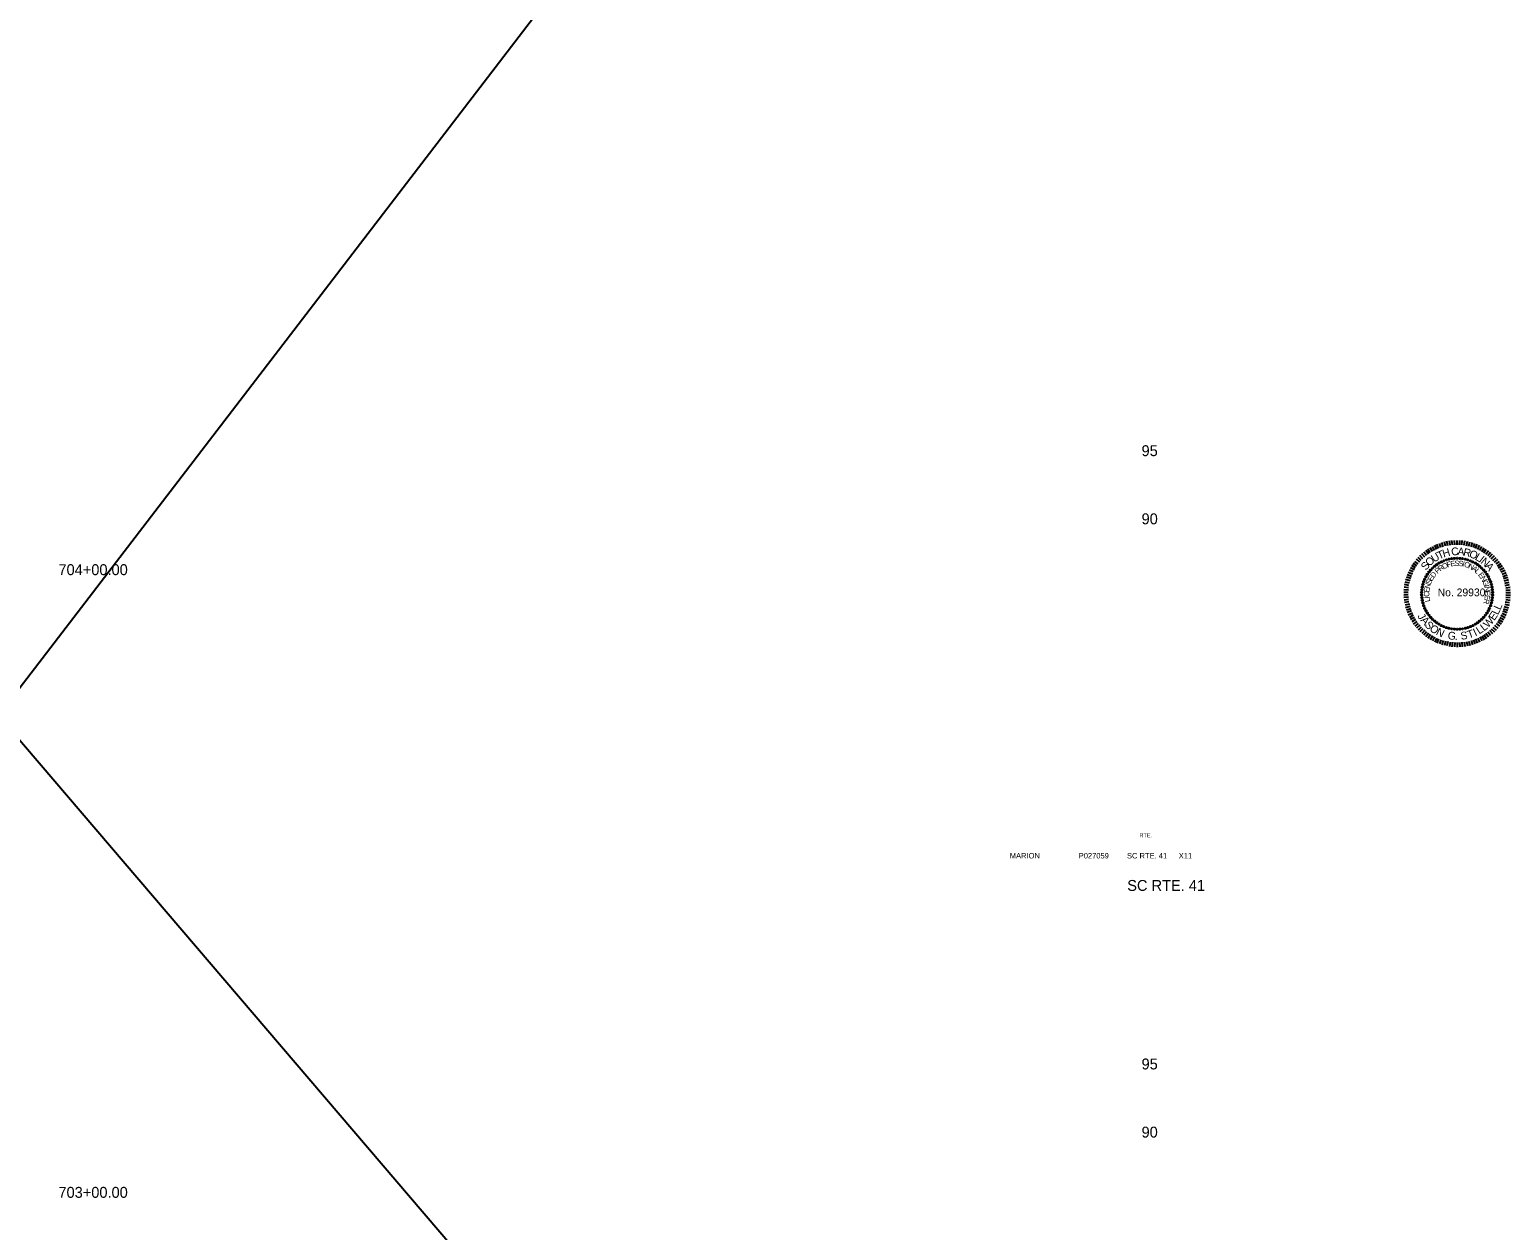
# Model space of a CAD drawing. Extents: x 952 to 1206, y 942 to 2399.
# Drawn here: x 1075.3 to 1184, y 2223.2 to 2311.3 of the extents above; entities that cross this region are included whole.
import ezdxf

# ---------------------------------------------------------------- set-up
doc = ezdxf.new("R2010")
doc.units = 0
for name, color, linetype in [('Default', 7, 'Continuous'), ('RD_SHT_TX', 7, 'Continuous'), ('RD_TX_PEShield', 7, 'Continuous'), ('RD_XS_TX_Elev_EX', 7, 'Continuous'), ('RD_XS_TX_Station', 7, 'Continuous')]:
    doc.layers.add(name, color=color, linetype=linetype)

# ---------------------------------------------------------------- blocks, each defined once
blk = doc.blocks.new('STILLWELL')
at = {"layer": 'RD_TX_PEShield'}
for p, q in [((-18.2, 30), (-19.9, 32.8)), ((-16.7, 30.8), (-18.2, 33.7)), ((-15.1, 31.6), (-16.5, 34.6)), ((-13.6, 32.3), (-14.8, 35.3)), ((-11.9, 32.9), (-13, 36)), ((-10.3, 33.4), (-11.2, 36.6)), ((-8.6, 33.9), (-9.4, 37.1)), ((-6.9, 34.3), (-7.5, 37.5)), ((-5.2, 34.6), (-5.7, 37.8)), ((-3.5, 34.8), (-3.8, 38)), ((-1.8, 34.9), (-1.9, 38.2)), ((0, 34.9), (0, 38.2)), ((1.7, 34.9), (1.9, 38.2)), ((3.4, 34.8), (3.7, 38)), ((5.2, 34.6), (5.6, 37.8)), ((6.9, 34.3), (7.5, 37.5)), ((8.6, 33.9), (9.3, 37.1)), ((10.2, 33.4), (11.2, 36.6)), ((11.9, 32.9), (13, 36)), ((13.5, 32.3), (14.7, 35.3)), ((15.1, 31.6), (16.5, 34.6)), ((16.6, 30.8), (18.2, 33.7)), ((18.2, 30), (19.8, 32.8)), ((-28.5, 20.9), (-31.1, 22.8)), ((-27.4, 22.2), (-29.9, 24.3)), ((-26.3, 23.5), (-28.7, 25.7)), ((-25.1, 24.7), (-27.4, 27.1)), ((-23.8, 25.9), (-26, 28.4)), ((-22.5, 27), (-24.5, 29.6)), ((-21.1, 28.1), (-23, 30.7)), ((-19.7, 29.1), (-21.5, 31.8)), ((19.6, 29.1), (21.4, 31.8)), ((21.1, 28.1), (23, 30.7)), ((22.4, 27), (24.5, 29.6)), ((23.8, 25.9), (25.9, 28.4)), ((25, 24.7), (27.3, 27.1)), ((26.2, 23.5), (28.6, 25.7)), ((27.4, 22.2), (29.9, 24.3)), ((28.5, 20.9), (31.1, 22.8)), ((-34.1, 10.2), (-37.2, 11.2)), ((-33.6, 11.8), (-36.6, 12.9)), ((-32.9, 13.4), (-35.9, 14.7)), ((-32.2, 15), (-35.1, 16.4)), ((-31.4, 16.5), (-34.2, 18.1)), ((-30.5, 18), (-33.3, 19.7)), ((-29.5, 19.4), (-32.2, 21.3)), ((29.5, 19.4), (32.2, 21.3)), ((30.4, 18), (33.2, 19.7)), ((31.3, 16.5), (34.2, 18.1)), ((32.1, 15), (35.1, 16.4)), ((32.9, 13.4), (35.9, 14.7)), ((33.5, 11.8), (36.6, 12.9)), ((34.1, 10.2), (37.2, 11.2)), ((-35.9, -0.1), (-39.2, 0)), ((-35.8, 1.7), (-39.1, 1.9)), ((-35.6, 3.4), (-38.9, 3.8)), ((-35.4, 5.1), (-38.6, 5.7)), ((-35.1, 6.8), (-38.2, 7.5)), ((-34.6, 8.5), (-37.8, 9.4)), ((34.6, 8.5), (37.7, 9.4)), ((35, 6.8), (38.2, 7.5)), ((35.3, 5.1), (38.5, 5.7)), ((35.6, 3.4), (38.8, 3.8)), ((35.7, 1.7), (39, 1.9)), ((35.8, -0.1), (39.1, 0)), ((-35.9, -1.8), (-39.2, -1.9)), ((-35.8, -3.5), (-39.1, -3.8)), ((-35.6, -5.3), (-38.9, -5.6)), ((-35.4, -7), (-38.6, -7.5)), ((-35.1, -8.7), (-38.2, -9.4)), ((-34.6, -10.4), (-37.8, -11.2)), ((34.6, -10.4), (37.7, -11.2)), ((35, -8.7), (38.2, -9.4)), ((35.3, -7), (38.5, -7.5)), ((35.6, -5.3), (38.8, -5.6)), ((35.7, -3.5), (39, -3.8)), ((35.8, -1.8), (39.1, -1.9)), ((-34.1, -12), (-37.2, -13)), ((-33.6, -13.6), (-36.6, -14.8)), ((-32.9, -15.3), (-35.9, -16.6)), ((-32.2, -16.8), (-35.1, -18.3)), ((-31.4, -18.4), (-34.2, -19.9)), ((-30.5, -19.9), (-33.3, -21.6)), ((-29.5, -21.3), (-32.2, -23.2)), ((29.5, -21.3), (32.2, -23.2)), ((30.4, -19.9), (33.2, -21.6)), ((31.3, -18.4), (34.2, -19.9)), ((32.1, -16.8), (35.1, -18.3)), ((32.9, -15.3), (35.9, -16.6)), ((33.5, -13.6), (36.6, -14.8)), ((34.1, -12), (37.2, -13)), ((-28.5, -22.7), (-31.1, -24.7)), ((-27.4, -24.1), (-29.9, -26.2)), ((-26.3, -25.4), (-28.7, -27.6)), ((-25.1, -26.6), (-27.4, -28.9)), ((-23.8, -27.8), (-26, -30.2)), ((-22.5, -28.9), (-24.5, -31.4)), ((-21.1, -29.9), (-23, -32.6)), ((-19.7, -30.9), (-21.5, -33.7)), ((-18.2, -31.8), (-19.9, -34.7)), ((18.2, -31.8), (19.8, -34.7)), ((19.6, -30.9), (21.4, -33.7)), ((21.1, -29.9), (23, -32.6)), ((22.4, -28.9), (24.5, -31.4)), ((23.8, -27.8), (25.9, -30.2)), ((25, -26.6), (27.3, -28.9)), ((26.2, -25.4), (28.6, -27.6)), ((27.4, -24.1), (29.9, -26.2)), ((28.5, -22.7), (31.1, -24.7)), ((-16.7, -32.7), (-18.2, -35.6)), ((-15.1, -33.5), (-16.5, -36.4)), ((-13.6, -34.1), (-14.8, -37.2)), ((-11.9, -34.8), (-13, -37.8)), ((-10.3, -35.3), (-11.2, -38.4)), ((-8.6, -35.8), (-9.4, -38.9)), ((-6.9, -36.1), (-7.5, -39.3)), ((-5.2, -36.4), (-5.7, -39.7)), ((-3.5, -36.6), (-3.8, -39.9)), ((-1.8, -36.8), (-1.9, -40)), ((0, -36.8), (0, -40.1)), ((1.7, -36.8), (1.9, -40)), ((3.4, -36.6), (3.7, -39.9)), ((5.2, -36.4), (5.6, -39.7)), ((6.9, -36.1), (7.5, -39.3)), ((8.6, -35.8), (9.3, -38.9)), ((10.2, -35.3), (11.2, -38.4)), ((11.9, -34.8), (13, -37.8)), ((13.5, -34.1), (14.7, -37.2)), ((15.1, -33.5), (16.5, -36.4)), ((16.6, -32.7), (18.2, -35.6))]:
    blk.add_line(p, q, dxfattribs=at)
for centre in [(-13.3, 21.5), (-11.6, 22.4), (-9.8, 23.2), (-7.9, 23.9), (-6, 24.4), (-4, 24.8), (-2, 25), (0, 25.1), (2, 25), (3.9, 24.8), (5.9, 24.4), (7.8, 23.9), (9.7, 23.2), (11.5, 22.4), (13.3, 21.5), (-22.9, 11.5), (-21.9, 13.2), (-20.7, 14.9), (-19.5, 16.4), (-18.1, 17.8), (-16.6, 19.2), (-15, 20.4), (15, 20.4), (16.5, 19.2), (18, 17.8), (19.4, 16.4), (20.7, 14.9), (21.8, 13.2), (22.9, 11.5), (-26.1, 0.1), (-25.9, 2.1), (-25.6, 4), (-25.1, 6), (-24.5, 7.9), (-23.8, 9.7), (23.7, 9.7), (24.5, 7.9), (25.1, 6), (25.5, 4), (25.8, 2.1), (26, 0.1), (-26.1, -1.9), (-25.9, -3.9), (-25.6, -5.9), (-25.1, -7.8), (-24.5, -9.7), (24.5, -9.7), (25.1, -7.8), (25.5, -5.9), (25.8, -3.9), (26, -1.9), (-23.8, -11.6), (-22.9, -13.4), (-21.9, -15.1), (-20.7, -16.7), (-19.5, -18.3), (-18.1, -19.7), (-16.6, -21), (16.5, -21), (18, -19.7), (19.4, -18.3), (20.7, -16.7), (21.8, -15.1), (22.9, -13.4), (23.7, -11.6), (-15, -22.2), (-13.3, -23.3), (-11.6, -24.3), (-9.8, -25.1), (-7.9, -25.8), (-6, -26.3), (-4, -26.7), (-2, -26.9), (0, -27), (2, -26.9), (3.9, -26.7), (5.9, -26.3), (7.8, -25.8), (9.7, -25.1), (11.5, -24.3), (13.3, -23.3), (15, -22.2)]:
    blk.add_circle(centre, 0.49, dxfattribs=at)
for s, height, rotation, p in [('C', 5.68, 4.076, (-4.2, 27.1)), ('A', 5.68, 355.3651, (0.1, 27.4)), ('S', 5.68, 49.6435, (-22.9, 15.8)), ('O', 5.68, 41.5972, (-20.4, 18.8)), ('U', 5.68, 32.2152, (-16.9, 21.8)), ('T', 5.68, 23.5044, (-13.2, 24.1)), ('H', 5.68, 16.1357, (-9.9, 25.6)), ('F', 3.92, 15.9995, (-7.1, 18.3)), ('E', 3.92, 8.9511, (-4.7, 19)), ('S', 3.92, 1.2546, (-1.9, 19.4)), ('S', 3.92, 353.558, (0.8, 19.5)), ('I', 3.92, 345.8615, (3.5, 19.2)), ('R', 5.68, 347.3188, (4.1, 27.1)), ('O', 3.92, 342.6583, (4.7, 19)), ('O', 5.68, 338.6079, (8.3, 26.2)), ('L', 5.68, 329.226, (12.6, 24.4)), ('I', 5.68, 322.5218, (15.5, 22.8)), ('N', 5.68, 319.1729, (16.8, 21.8)), ('E', 3.92, 60.2341, (-18.5, 7.9)), ('D', 3.92, 52.5376, (-17.1, 10.3)), ('P', 3.92, 41.0022, (-14.5, 13.5)), ('R', 3.92, 33.3057, (-12.5, 15.3)), ('O', 3.92, 24.9735, (-10, 16.9)), ('N', 3.92, 333.6842, (7.7, 18)), ('A', 3.92, 325.3521, (10.4, 16.7)), ('L', 3.92, 317.6555, (12.6, 15.1)), ('E', 3.92, 308.0396, (15.1, 12.8)), ('N', 3.92, 300.343, (16.8, 10.6)), ('A', 5.68, 310.4621, (20.1, 19)), ('C', 3.92, 92.2915, (-20.4, -3.2)), ('E', 3.92, 83.9594, (-20.5, -0.2)), ('N', 3.92, 76.2628, (-20.2, 2.5)), ('S', 3.92, 67.9307, (-19.5, 5.4)), ('G', 3.92, 292.0109, (18.3, 8.1)), ('I', 3.92, 283.0368, (19.5, 5.1)), ('N', 3.92, 279.8336, (19.8, 4)), ('E', 3.92, 271.5014, (20.3, 1.1)), ('I', 3.92, 95.4947, (-20.2, -4.3)), ('L', 3.92, 101.9075, (-19.7, -6.6)), ('R', 3.92, 256.1083, (20.1, -4.4)), ('E', 3.92, 263.8049, (20.4, -1.7)), ('L', 5.68, 65.098, (31.6, -13.3)), ('J', 5.68, 299.033, (-29.4, -17.3)), ('A', 5.68, 310.5887, (-27.2, -20.6)), ('S', 5.68, 310.5887, (-24.3, -24)), ('W', 5.68, 47.0518, (22.6, -26.4)), ('E', 5.68, 56.4327, (27.3, -21.1)), ('L', 5.68, 65.098, (30, -16.9)), ('O', 5.68, 321.0072, (-20.8, -27.4)), ('N', 5.68, 333.4326, (-16, -30.8)), ('G', 5.68, 352.2045, (-7.2, -34.2)), ('S', 5.68, 8.0826, (2.9, -34.8)), ('T', 5.68, 18.9019, (8.5, -33.9)), ('I', 5.68, 25.3991, (13.3, -32.2)), ('L', 5.68, 34.0644, (16.2, -30.9)), ('L', 5.68, 37.6708, (19.6, -28.7)), ('.', 5.68, 0.8698, (-1.8, -34.9))]:
    blk.add_text(s, height=height, rotation=rotation, dxfattribs=at).set_placement(p)
blk.add_text('No. 29930', height=5.68, dxfattribs=at).set_placement((-14.3, -2.8))

msp = doc.modelspace()

# ---------------------------------------------------------------- linework, layer by layer
at = {"layer": 'RD_SHT_TX'}
for p, q in [((976.8, 2135.43), (1179.13, 2399.4)), ((966.94, 2385.17), (1175.94, 2140.52))]:
    msp.add_line(p, q, dxfattribs=at)

# ---------------------------------------------------------------- block references
at = {"layer": 'Default', "xscale": 0.1, "yscale": 0.10000000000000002}
msp.add_blockref('STILLWELL', (1180.08, 2270), dxfattribs=at)

# ---------------------------------------------------------------- texts
at = {"layer": 'RD_SHT_TX'}
for s, height, p in [('RTE.', 0.3, (1156.76, 2252.03)), ('MARION', 0.4, (1147.25, 2250.48)), ('P027059', 0.4, (1152.31, 2250.48)), ('SC RTE. 41', 0.4, (1155.85, 2250.48)), ('X11', 0.4, (1159.65, 2250.48)), ('SC RTE. 41', 0.8, (1155.87, 2248.1))]:
    msp.add_text(s, height=height, dxfattribs=at).set_placement(p)
at = {"layer": 'RD_XS_TX_Elev_EX'}
for s, p in [('95', (1156.92, 2280)), ('90', (1156.92, 2275)), ('95', (1156.92, 2235)), ('90', (1156.92, 2230))]:
    msp.add_text(s, height=0.8, dxfattribs=at).set_placement(p)
at = {"layer": 'RD_XS_TX_Station'}
for s, p in [('704+00.00', (1077.44, 2271.27)), ('703+00.00', (1077.44, 2225.58))]:
    msp.add_text(s, height=0.8, dxfattribs=at).set_placement(p)

doc.saveas('drawing.dxf')
